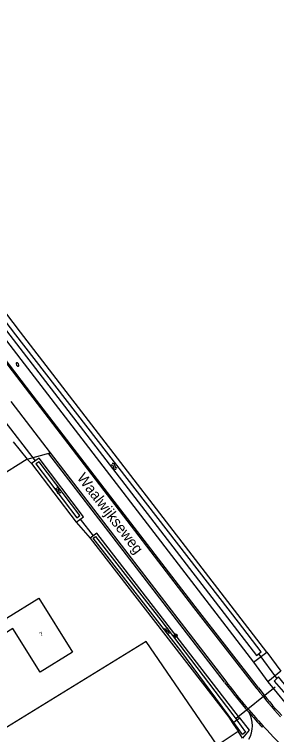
# Model space of a CAD drawing. Extents: x 136000 to 141000, y 400494 to 402006.
# Drawn here: x 136514.7 to 136576.3, y 401405.3 to 401574.8 of the extents above; entities that cross this region are included whole.
import ezdxf

# ---------------------------------------------------------------- set-up
doc = ezdxf.new("R2010")
doc.units = 0
for name, color, linetype in [('gg-anno-huisnummerreeks BGT', 7, 'Continuous'), ('gg-anno-openbare ruimte label', 7, 'Continuous'), ('gg-bbg-hoofdgebouw', 7, 'Continuous'), ('gg-knt-bronhoudergrens', 7, 'Continuous'), ('gg-knt-onverhard', 7, 'Continuous'), ('gg-knt-verharding', 7, 'Continuous'), ('gg-kntw-bovenkant insteek waterloop', 7, 'Continuous'), ('gg-kntw-waterlijn', 7, 'Continuous'), ('gg-kwrk-duiker nz buis', 7, 'Continuous'), ('gt-grn-groengrens', 7, 'Continuous'), ('gt-symb-boom', 7, 'Continuous'), ('gt-symb-brandkraan', 7, 'Continuous'), ('gt-symb-watersymbool', 7, 'Continuous'), ('gx-grn-maaiveld', 7, 'Continuous')]:
    doc.layers.add(name, color=color, linetype=linetype)

# ---------------------------------------------------------------- blocks, each defined once
blk = doc.blocks.new('gt0-BR')
at = {"layer": 'gt-symb-brandkraan'}
for centre, radius, start, end in [((-0.24, 0), 0.206, 107.5669, 252.4331), ((0.6, -2.66), 3, 106.892, 107.5669), ((0, -0.69), 0.938, 73.108, 106.892), ((-0.6, -2.66), 3, 72.4331, 73.108), ((0.24, 0), 0.206, 287.567, 72.4331), ((0.6, 2.66), 3, 252.4331, 253.108), ((0, 0.69), 0.938, 253.108, 286.8921), ((-0.6, 2.66), 3, 286.8921, 287.567)]:
    blk.add_arc(centre, radius, start, end, dxfattribs=at)
blk = doc.blocks.new('gt0-WA')
at = {"layer": 'gt-symb-watersymbool'}
for centre, start, end in [((-0.32, 0.02), 28.0725, 151.9275), ((0.43, 0.42), 208.0725, 331.9275), ((-0.32, -0.43), 28.0725, 151.9275), ((0.43, -0.03), 208.0725, 331.9275)]:
    blk.add_arc(centre, 0.425, start, end, dxfattribs=at)
blk = doc.blocks.new('gt0-BOOM')
at = {"layer": 'gt-symb-boom'}
for radius in [0.4, 0.2]:
    blk.add_circle((0, 0), radius, dxfattribs=at)

msp = doc.modelspace()

# ---------------------------------------------------------------- linework, layer by layer
at = {"layer": 'gg-bbg-hoofdgebouw'}
msp.add_lwpolyline([(136507.63, 401436.29), (136510.83, 401431.17), (136512.96, 401432.49), (136512.84, 401432.68), (136520.48, 401437.42), (136528.4, 401424.7), (136520.79, 401419.95), (136514.36, 401430.25), (136512.23, 401428.93), (136512.34, 401428.75), (136506.82, 401425.3), (136502.12, 401432.85), (136507.63, 401436.29)], dxfattribs=at)
at = {"layer": 'gg-knt-bronhoudergrens'}
msp.add_line((136574.03, 401424.72), (136577.31, 401420.24), dxfattribs=at)
at = {"layer": 'gg-knt-onverhard'}
msp.add_arc((136564.43, 401407.34), 6.26, 329.8781, 30.6109, dxfattribs=at)
at = {"layer": 'gg-knt-verharding'}
for p, q in [((136513.9, 401483.67), (136523.15, 401471.62)), ((136514.46, 401474.15), (136517.73, 401470.12)), ((136517.73, 401470.12), (136523.15, 401471.62)), ((136517.73, 401470.12), (136503.81, 401461.37)), ((136572.94, 401407.02), (136573.22, 401407.29))]:
    msp.add_line(p, q, dxfattribs=at)
for points in [[(136571.77, 401416.07), (136556.92, 401435.18), (136517.33, 401486.85), (136482.95, 401531.83)], [(136572.06, 401416.32), (136557.22, 401435.41), (136517.61, 401487.08), (136483.25, 401532.07), (136483.01, 401531.88)], [(136564.12, 401417.59), (136552.8, 401432.29), (136522.84, 401471.38), (136523.15, 401471.62)], [(136523.15, 401471.62), (136553.13, 401432.49), (136564.38, 401417.86)]]:
    msp.add_lwpolyline(points, dxfattribs=at)
for centre, radius, start, end in [((136678.1, 401503.95), 142.63, 217.1289, 222.6654), ((136679.39, 401504.77), 144.53, 217.1017, 220.6974), ((136649.79, 401475.29), 97.94, 217.1999, 222.2321), ((136635.71, 401464.34), 79.73, 217.0267, 223.1778), ((136680.84, 401506.06), 146.47, 220.7082, 222.5467), ((136683.55, 401507.56), 149.1, 222.2657, 225.9346)]:
    msp.add_arc(centre, radius, start, end, dxfattribs=at)
at = {"layer": 'gg-kntw-bovenkant insteek waterloop'}
for p, q in [((136516.17, 401500), (136459.28, 401574.02)), ((136511.25, 401500), (136570.93, 401422.34)), ((136574.03, 401424.72), (136516.17, 401500)), ((136518.79, 401469.07), (136529.24, 401455.28)), ((136570.93, 401422.34), (136574.03, 401424.72)), ((136577.31, 401420.24), (136574.29, 401417.68)), ((136566.05, 401407.93), (136567.29, 401406.06))]:
    msp.add_line(p, q, dxfattribs=at)
for points in [[(136529.24, 401455.28), (136530.97, 401456.55), (136520.53, 401470.35), (136518.79, 401469.07)], [(136567.64, 401409.21), (136534.09, 401452.67), (136532.53, 401451.55)], [(136532.53, 401451.55), (136565.1, 401409.37), (136566.05, 401407.93)], [(136574.29, 401417.68), (136580.48, 401410.16), (136583.69, 401412.47)], [(136567.64, 401409.21), (136569.89, 401406.3), (136568.36, 401404.45), (136567.29, 401406.06)]]:
    msp.add_lwpolyline(points, dxfattribs=at)
at = {"layer": 'gg-kntw-waterlijn'}
for points in [[(136456.52, 401573.69), (136467.17, 401559.65), (136530.96, 401476.74), (136571.62, 401423.9), (136572.74, 401424.76), (136567.37, 401431.74), (136515.05, 401499.39), (136478.73, 401546.95), (136457.08, 401574.76), (136456.7, 401574.47), (136456.52, 401573.69)], [(136519.77, 401469.01), (136529.41, 401456.26), (136530.13, 401456.81), (136520.58, 401469.45), (136519.77, 401469.01)], [(136566.28, 401408.12), (136553.87, 401424.98), (136533.24, 401451.54), (136533.8, 401451.88), (136549.14, 401432.23), (136566.09, 401409.92), (136566.99, 401408.69)], [(136575.79, 401417.84), (136581.22, 401411.57), (136582.07, 401412.42), (136576.78, 401418.89), (136575.79, 401417.84)], [(136566.99, 401408.69), (136569.07, 401405.87), (136568.33, 401405.33), (136566.28, 401408.12)]]:
    msp.add_lwpolyline(points, dxfattribs=at)
at = {"layer": 'gg-kwrk-duiker nz buis'}
for p, q in [((136519.67, 401469.72), (136512.55, 401478.93)), ((136530.22, 401456), (136533.26, 401452.07)), ((136572.17, 401424.18), (136576.29, 401418.55)), ((136566.86, 401409.15), (136575.98, 401416.49))]:
    msp.add_line(p, q, dxfattribs=at)
at = {"layer": 'gt-grn-groengrens'}
for p, q in [((136517.73, 401470.12), (136518.79, 401469.07)), ((136529.24, 401455.28), (136532.53, 401451.55)), ((136570.93, 401422.34), (136574.29, 401417.68)), ((136562.37, 401402.8), (136567.29, 401406.06))]:
    msp.add_line(p, q, dxfattribs=at)
msp.add_lwpolyline([(136562.37, 401402.8), (136545.7, 401427.16), (136496.72, 401397.05), (136480.22, 401423.9)], dxfattribs=at)
at = {"layer": 'gx-grn-maaiveld'}
for p, q in [((136566.99, 401408.69), (136567.64, 401409.21)), ((136566.05, 401407.93), (136566.28, 401408.12)), ((136566.99, 401408.69), (136566.28, 401408.12))]:
    msp.add_line(p, q, dxfattribs=at)

# ---------------------------------------------------------------- block references
at = {"layer": 'gt-symb-boom', "rotation": 90}
msp.add_blockref('gt0-BOOM', (136552.62, 401428.56), dxfattribs=at)
at = {"layer": 'gt-symb-brandkraan', "rotation": -58.12218352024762}
msp.add_blockref('gt0-BR', (136515.46, 401492.38), dxfattribs=at)
at = {"layer": 'gt-symb-watersymbool'}
for p, rotation in [((136538.13, 401468.44), -38.990994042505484), ((136524.96, 401462.74), -52.843625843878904), ((136550.62, 401429.73), -52.35108357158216)]:
    msp.add_blockref('gt0-WA', p, dxfattribs=dict(at, rotation=rotation))

# ---------------------------------------------------------------- texts
at = {"layer": 'gg-anno-huisnummerreeks BGT'}
msp.add_text('7', height=1, rotation=31.9, dxfattribs=at).set_placement((136520.98, 401428.31))
at = {"layer": 'gg-anno-openbare ruimte label'}
msp.add_text('Waalwijkseweg', height=2.5, rotation=307.6, dxfattribs=at).set_placement((136529.31, 401465.66))

doc.saveas('drawing.dxf')
